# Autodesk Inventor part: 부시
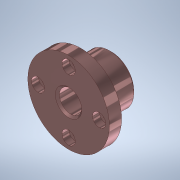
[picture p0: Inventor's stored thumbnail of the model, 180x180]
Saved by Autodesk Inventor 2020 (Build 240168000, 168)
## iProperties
Created: 2023-08
Part Number: 부시
Material: 스테인리스강
Document SubType Name: Modeling
Designer: mdu-01
Density: 8.08 g/cm^3
Appearance: 반광택(1)
Mass: 94.6245 g
Surface Area: 51.6669 cm^2
Volume: 11.7109 cm^3
Author: mdu-01
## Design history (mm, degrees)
sketch "스케치1"
  geometry: L1 (0, 0)-(0, 25); L2 (-5.5, 1)-(5.5, 1) reference; L3 (5.5, 24)-(5.5, 5); L4 (12, 24)-(12, 10); L5 (6.5, 4)-(20, 4); L6 (20, 4)-(20, 10); L7 (12, 10)-(20, 10); L8 (6.5, 25)-(11, 25); L9 (5.5, 24)-(6.5, 25); L10 (12, 24)-(11, 25); L11 (5.5, 5)-(6.5, 4); L12 (-21, 10)-(21, 10) reference; L13 (12, 30)-(12, 11) reference; L14 (21, 10)-(21, 0) reference; 2 further points
  constraints: 24 end point, 6 point on line, 3 perpendicular, 3 vertical, 2 collinear, 1 horizontal, 4 other
  dimensions: "d3" = 1 distance of L3.start point (5.5, 25); "d4" = 1 distance of L8.start point (5.5, 25) (= d3); "d7" = 1 distance of L3.end point (5.5, 4) (= d3); "d8" = 1 distance of L5.start point (5.5, 4) (= d7); "d10" = 21 distance between parallel lines of L8 L5; "d13" = 4 distance from line of L5 L1.start; "d16" = 1 distance from line of L8.end L4; "d17" = 1 distance from line of L4.start L8; "d26" = 1 distance between parallel lines of L14 L6
revolve "회전1" sketch "스케치1" stored, may be unused: angle "d9" = 90 deg
sketch "스케치2" dims "d18" = 30
  geometry: 3 further points
  constraints: 2 vertical alignment, 1 coincident, 2 other
hole "구멍1" sketch "스케치2" at (0, 15) diameter "d19" = 3.4; stored, may be unused: countersink angle "d23" = 90 deg, drill point angle "d25" = 118 deg; dims "d20" = 6, "d21" = 6.5, "d22" = 3.4, "d24" = 8
node "솔리드1"
pattern_circular "원형 패턴1" dims angle "d28" = 360 deg
node "참조2"
node "참조4"
